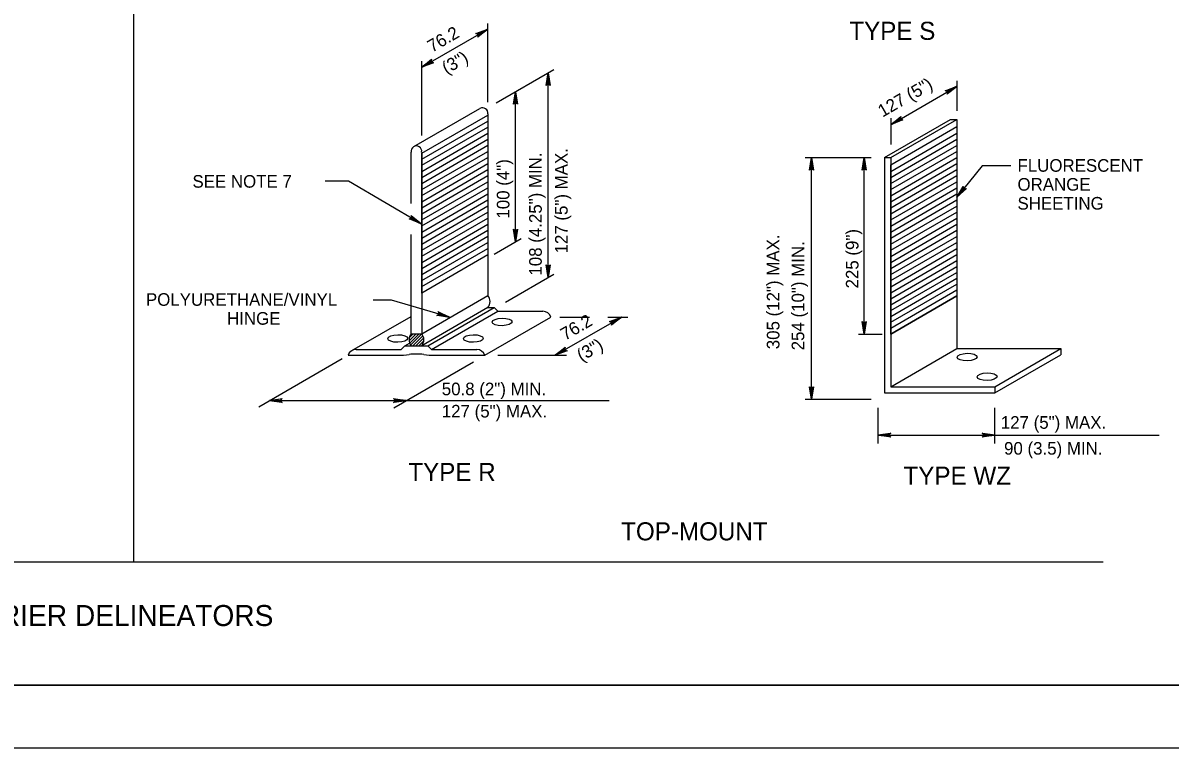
# Model space of a CAD drawing. Extents: x 640253 to 641999, y 298458 to 299646.
# Drawn here: x 640526.1 to 640798.8, y 298457.6 to 298630.1 of the extents above; entities that cross this region are included whole.
import ezdxf

# ---------------------------------------------------------------- set-up
doc = ezdxf.new("R2010")
doc.units = 0
for name, color, linetype in [('1', 7, 'Continuous'), ('2', 7, 'Continuous'), ('PLT-BNDY', 7, 'Continuous')]:
    doc.layers.add(name, color=color, linetype=linetype)

msp = doc.modelspace()

# ---------------------------------------------------------------- linework, layer by layer
at = {"layer": '1'}
for p, q in [((640552.4, 298501.97), (640552.4, 298787.67)), ((640318.26, 298501.97), (640782.88, 298501.97)), ((641079.31, 298472.63), (640293.31, 298472.63)), ((640293.31, 298472.63), (640879.31, 298472.63))]:
    msp.add_line(p, q, dxfattribs=at)
at = {"layer": '2'}
for p, q in [((640636.6, 298611.27), (640636.6, 298629.99)), ((640620.86, 298619.6), (640636.6, 298628.69)), ((640620.86, 298603.34), (640620.86, 298621.06)), ((640638.58, 298611.11), (640652.31, 298619.04)), ((640650.95, 298569.6), (640650.95, 298618.26)), ((640748.2, 298609.2), (640748.2, 298616.39)), ((640643.19, 298578.08), (640643.19, 298613.77)), ((640732.46, 298605.99), (640748.2, 298615.08)), ((640618.97, 298600.71), (640634.72, 298609.8)), ((640636.6, 298608.5), (640636.6, 298565.29)), ((640730.89, 298598.1), (640746.63, 298607.19)), ((640732.39, 298598.1), (640748.13, 298607.19)), ((640732.46, 298601.21), (640732.46, 298607.46)), ((640746.63, 298607.19), (640748.13, 298607.19)), ((640748.13, 298607.19), (640748.13, 298552.69)), ((640620.86, 298597.71), (640636.6, 298606.8)), ((640620.86, 298596.27), (640636.6, 298605.36)), ((640620.86, 298594.82), (640636.6, 298603.91)), ((640620.86, 298593.38), (640636.6, 298602.47)), ((640732.39, 298594.81), (640748.13, 298603.9)), ((640732.39, 298593.37), (640748.13, 298602.46)), ((640618.36, 298587.14), (640618.36, 298599.41)), ((640620.86, 298591.94), (640636.6, 298601.02)), ((640620.86, 298590.49), (640636.6, 298599.58)), ((640620.86, 298599.41), (640620.86, 298556.2)), ((640620.86, 298598.88), (640621.08, 298599.28)), ((640620.86, 298598.91), (640621.05, 298599.26)), ((640732.39, 298591.92), (640748.13, 298601.01)), ((640732.39, 298590.48), (640748.13, 298599.57)), ((640620.86, 298589.05), (640636.6, 298598.14)), ((640620.86, 298587.61), (640636.6, 298596.69)), ((640712.01, 298598.1), (640727.76, 298598.1)), ((640713.55, 298540.6), (640713.55, 298598.1)), ((640726.09, 298556.11), (640726.09, 298598.1)), ((640730.89, 298598.1), (640732.39, 298598.1)), ((640730.89, 298598.1), (640730.89, 298542.1)), ((640732.39, 298589.04), (640748.13, 298598.13)), ((640732.39, 298598.1), (640732.39, 298543.6)), ((640732.39, 298587.59), (640748.13, 298596.68)), ((640732.39, 298596.1), (640732.61, 298596.5)), ((640732.39, 298596.14), (640732.58, 298596.48)), ((640620.86, 298586.16), (640636.6, 298595.25)), ((640620.86, 298584.72), (640636.6, 298593.81)), ((640732.39, 298586.15), (640748.13, 298595.24)), ((640732.39, 298584.71), (640748.13, 298593.8)), ((640754.14, 298596.12), (640748.13, 298588.7)), ((640760.91, 298596.12), (640754.14, 298596.12)), ((640603.45, 298592.49), (640597.95, 298592.49)), ((640620.73, 298582.38), (640603.45, 298592.49)), ((640620.86, 298583.28), (640636.6, 298592.36)), ((640620.86, 298581.83), (640636.6, 298590.92)), ((640732.39, 298583.26), (640748.13, 298592.35)), ((640732.39, 298581.82), (640748.13, 298590.91)), ((640620.86, 298580.39), (640636.6, 298589.48)), ((640620.86, 298578.94), (640636.6, 298588.03)), ((640732.39, 298580.38), (640748.13, 298589.47)), ((640732.39, 298578.93), (640748.13, 298588.02)), ((640620.86, 298577.5), (640636.6, 298586.59)), ((640732.39, 298577.49), (640748.13, 298586.58)), ((640620.86, 298576.06), (640636.6, 298585.15)), ((640620.86, 298574.62), (640636.6, 298583.7)), ((640732.39, 298576.05), (640748.13, 298585.14)), ((640732.39, 298574.6), (640748.13, 298583.69)), ((640620.86, 298573.17), (640636.6, 298582.26)), ((640620.86, 298571.73), (640636.6, 298580.82)), ((640732.39, 298573.16), (640748.13, 298582.25)), ((640732.39, 298571.72), (640748.13, 298580.81)), ((640618.36, 298556.2), (640618.36, 298579.81)), ((640620.86, 298570.28), (640636.6, 298579.37)), ((640620.86, 298568.84), (640636.6, 298577.93)), ((640638.07, 298575.12), (640644.5, 298578.83)), ((640732.39, 298570.27), (640748.13, 298579.36)), ((640732.39, 298568.83), (640748.13, 298577.92)), ((640620.86, 298567.4), (640636.6, 298576.49)), ((640732.39, 298567.39), (640748.13, 298576.48)), ((640732.39, 298565.94), (640748.13, 298575.03)), ((640732.39, 298564.5), (640748.13, 298573.59)), ((640732.39, 298563.1), (640748.13, 298572.19)), ((640640.76, 298563.72), (640652.31, 298570.39)), ((640732.39, 298561.71), (640748.13, 298570.79)), ((640732.39, 298560.31), (640748.13, 298569.4)), ((640732.39, 298558.91), (640748.13, 298568)), ((640732.39, 298557.51), (640748.13, 298566.6)), ((640613.67, 298564.19), (640609.34, 298564.19)), ((640627.46, 298560.15), (640613.67, 298564.19)), ((640620.86, 298556.2), (640636.6, 298565.29)), ((640732.39, 298556.11), (640748.13, 298565.2)), ((640636.6, 298562.41), (640620.86, 298553.31)), ((640622.36, 298553.31), (640638.1, 298562.41)), ((640623.23, 298552.44), (640638.98, 298561.53)), ((640636.6, 298562.41), (640638.1, 298562.41)), ((640638.1, 298562.41), (640638.98, 298561.53)), ((640638.98, 298561.53), (640649.7, 298561.53)), ((640604.27, 298552.17), (640618.36, 298560.31)), ((640635.85, 298551.06), (640651.6, 298560.16)), ((640652.59, 298551.06), (640668.35, 298560.16)), ((640653.68, 298560.16), (640660.77, 298560.16)), ((640665.09, 298560.16), (640669.88, 298560.16)), ((640617.88, 298554.53), (640619.55, 298556.2)), ((640617.95, 298555.31), (640618.84, 298556.2)), ((640618.01, 298553.96), (640620.26, 298556.2)), ((640618.24, 298553.48), (640620.9, 298556.14)), ((640618.36, 298556.2), (640620.86, 298556.2)), ((640618.78, 298553.31), (640621.17, 298555.7)), ((640724.73, 298556.11), (640730.31, 298556.11)), ((640616.86, 298553.31), (640615.98, 298552.44)), ((640616.86, 298553.31), (640617.98, 298553.96)), ((640616.86, 298553.31), (640622.36, 298553.31)), ((640619.49, 298553.31), (640621.32, 298555.15)), ((640620.2, 298553.31), (640621.33, 298554.45)), ((640620.86, 298553.31), (640620.86, 298553.32)), ((640622.36, 298553.31), (640623.23, 298552.44)), ((640732.39, 298543.6), (640748.13, 298552.69)), ((640748.13, 298552.69), (640772.85, 298552.69)), ((640757.1, 298543.6), (640772.85, 298552.69)), ((640772.85, 298552.69), (640772.85, 298551.2)), ((640582.11, 298538.79), (640601.98, 298550.27)), ((640603.36, 298551.06), (640615.26, 298551.06)), ((640605.26, 298552.44), (640615.98, 298552.44)), ((640623.23, 298552.44), (640633.95, 298552.44)), ((640623.96, 298551.06), (640635.85, 298551.06)), ((640638.93, 298551.06), (640655.32, 298551.06)), ((640757.1, 298542.1), (640772.85, 298551.2)), ((640614.25, 298538.6), (640633.17, 298549.52)), ((640730.89, 298542.1), (640757.1, 298542.1)), ((640732.39, 298543.6), (640757.1, 298543.6)), ((640757.1, 298543.6), (640757.1, 298542.1)), ((640584.7, 298540.29), (640665.44, 298540.29)), ((640712.01, 298540.6), (640727.76, 298540.6)), ((640729.39, 298530.05), (640729.39, 298538.56)), ((640757.1, 298530.05), (640757.1, 298538.56)), ((640729.39, 298532.09), (640796.22, 298532.09))]:
    msp.add_line(p, q, dxfattribs=at)
for points in [[(640633.95, 298627.57), (640634.14, 298627.45), (640636.6, 298628.69), (640633.95, 298627.57), (640633.76, 298627.61), (640636.6, 298628.69), (640634.29, 298627.2), (640634.3, 298626.97), (640636.6, 298628.69), (640634.24, 298626.78), (640634.3, 298626.97)], [(640623.51, 298620.71), (640623.31, 298620.84), (640620.86, 298619.6), (640623.51, 298620.71), (640623.7, 298620.68), (640620.86, 298619.6), (640623.17, 298621.09), (640623.15, 298621.31), (640620.86, 298619.6), (640623.22, 298621.51), (640623.15, 298621.31)], [(640650.6, 298615.4), (640650.8, 298615.51), (640650.95, 298618.26), (640650.6, 298615.4), (640650.47, 298615.26), (640650.95, 298618.26), (640651.09, 298615.51), (640651.29, 298615.41), (640650.95, 298618.26), (640651.43, 298615.26), (640651.29, 298615.41)], [(640642.83, 298610.92), (640643.04, 298611.03), (640643.19, 298613.77), (640642.83, 298610.92), (640642.71, 298610.77), (640643.19, 298613.77), (640643.33, 298611.03), (640643.53, 298610.93), (640643.19, 298613.77), (640643.67, 298610.77), (640643.53, 298610.93)], [(640745.55, 298613.97), (640745.75, 298613.84), (640748.2, 298615.08), (640745.55, 298613.97), (640745.36, 298614), (640748.2, 298615.08), (640745.89, 298613.59), (640745.91, 298613.37), (640748.2, 298615.08), (640745.84, 298613.17), (640745.91, 298613.37)], [(640735.11, 298607.11), (640734.91, 298607.24), (640732.46, 298605.99), (640735.11, 298607.11), (640735.3, 298607.08), (640732.46, 298605.99), (640734.77, 298607.48), (640734.75, 298607.71), (640732.46, 298605.99), (640734.82, 298607.91), (640734.75, 298607.71)], [(640713.19, 298595.25), (640713.4, 298595.36), (640713.55, 298598.1), (640713.19, 298595.25), (640713.06, 298595.1), (640713.55, 298598.1), (640713.68, 298595.36), (640713.89, 298595.26), (640713.55, 298598.1), (640714.02, 298595.1), (640713.89, 298595.26)], [(640725.73, 298595.25), (640725.94, 298595.36), (640726.09, 298598.1), (640725.73, 298595.25), (640725.61, 298595.1), (640726.09, 298598.1), (640726.22, 298595.36), (640726.43, 298595.26), (640726.09, 298598.1), (640726.57, 298595.1), (640726.43, 298595.26)], [(640750.2, 298590.69), (640749.97, 298590.74), (640748.13, 298588.7), (640750.2, 298590.69), (640750.39, 298590.73), (640748.13, 298588.7), (640749.75, 298590.92), (640749.65, 298591.13), (640748.13, 298588.7), (640749.64, 298591.33), (640749.65, 298591.13)], [(640618.46, 298584.15), (640618.44, 298583.92), (640620.73, 298582.38), (640618.46, 298584.15), (640618.4, 298584.34), (640620.73, 298582.38), (640618.3, 298583.67), (640618.11, 298583.55), (640620.73, 298582.38), (640617.9, 298583.51), (640618.11, 298583.55)], [(640643.55, 298580.93), (640643.35, 298580.83), (640643.19, 298578.08), (640643.55, 298580.93), (640643.68, 298581.08), (640643.19, 298578.08), (640643.06, 298580.83), (640642.85, 298580.93), (640643.19, 298578.08), (640642.72, 298581.08), (640642.85, 298580.93)], [(640651.31, 298572.46), (640651.11, 298572.35), (640650.95, 298569.6), (640651.31, 298572.46), (640651.44, 298572.6), (640650.95, 298569.6), (640650.82, 298572.35), (640650.61, 298572.45), (640650.95, 298569.6), (640650.48, 298572.6), (640650.61, 298572.45)], [(640624.82, 298561.29), (640624.87, 298561.07), (640627.46, 298560.15), (640624.82, 298561.29), (640624.72, 298561.45), (640627.46, 298560.15), (640624.79, 298560.79), (640624.63, 298560.62), (640627.46, 298560.15), (640624.45, 298560.53), (640624.63, 298560.62)], [(640665.7, 298559.04), (640665.89, 298558.92), (640668.35, 298560.16), (640665.7, 298559.04), (640665.51, 298559.08), (640668.35, 298560.16), (640666.04, 298558.67), (640666.05, 298558.44), (640668.35, 298560.16), (640665.99, 298558.24), (640666.05, 298558.44)], [(640726.45, 298558.97), (640726.24, 298558.86), (640726.09, 298556.11), (640726.45, 298558.97), (640726.57, 298559.11), (640726.09, 298556.11), (640725.95, 298558.86), (640725.75, 298558.96), (640726.09, 298556.11), (640725.61, 298559.11), (640725.75, 298558.96)], [(640655.24, 298552.18), (640655.05, 298552.31), (640652.59, 298551.06), (640655.24, 298552.18), (640655.43, 298552.14), (640652.59, 298551.06), (640654.9, 298552.55), (640654.89, 298552.78), (640652.59, 298551.06), (640654.95, 298552.98), (640654.89, 298552.78)], [(640713.91, 298543.46), (640713.7, 298543.35), (640713.55, 298540.6), (640713.91, 298543.46), (640714.03, 298543.6), (640713.55, 298540.6), (640713.41, 298543.35), (640713.21, 298543.45), (640713.55, 298540.6), (640713.07, 298543.6), (640713.21, 298543.45)], [(640587.56, 298539.93), (640587.45, 298540.14), (640584.7, 298540.29), (640587.56, 298539.93), (640587.7, 298539.81), (640584.7, 298540.29), (640587.45, 298540.43), (640587.55, 298540.63), (640584.7, 298540.29), (640587.7, 298540.77), (640587.55, 298540.63)], [(640614.34, 298540.65), (640614.44, 298540.45), (640617.19, 298540.29), (640614.34, 298540.65), (640614.19, 298540.78), (640617.19, 298540.29), (640614.45, 298540.16), (640614.35, 298539.95), (640617.19, 298540.29), (640614.19, 298539.82), (640614.35, 298539.95)], [(640732.24, 298531.74), (640732.14, 298531.94), (640729.39, 298532.09), (640732.24, 298531.74), (640732.39, 298531.61), (640729.39, 298532.09), (640732.13, 298532.23), (640732.23, 298532.43), (640729.39, 298532.09), (640732.39, 298532.57), (640732.23, 298532.43)], [(640754.25, 298532.45), (640754.36, 298532.25), (640757.1, 298532.09), (640754.25, 298532.45), (640754.1, 298532.58), (640757.1, 298532.09), (640754.36, 298531.96), (640754.26, 298531.76), (640757.1, 298532.09), (640754.1, 298531.62), (640754.26, 298531.76)]]:
    msp.add_lwpolyline(points, dxfattribs=at)
for points in [[(640620.86, 298565.88), (640620.86, 298599.14), (640636.6, 298608.23), (640636.6, 298574.97)], [(640732.39, 298556.11), (640732.39, 298596.37), (640748.13, 298605.46), (640748.13, 298565.2)]]:
    msp.add_lwpolyline(points, close=True, dxfattribs=at)
for centre, radius, start, end in [((640635.35, 298608.7), 1.26, 350.9133, 119.9792), ((640619.61, 298599.61), 1.26, 350.9133, 189.0867), ((640634.82, 298563.85), 2.29, 320.9923, 39.0623), ((640649.7, 298559.53), 2, 18.187, 90), ((640620.14, 298554.76), 2.29, 140.9377, 219.0623), ((640619.08, 298554.76), 2.29, 320.9923, 39.0623), ((640605.26, 298550.44), 2, 90, 161.79), ((640615.26, 298569.81), 18.75, 270, 278.0038), ((640619.61, 298538.87), 12.5, 81.9962, 98.0038), ((640623.96, 298569.81), 18.75, 261.9962, 270), ((640633.95, 298550.44), 2, 18.21, 90)]:
    msp.add_arc(centre, radius, start, end, dxfattribs=at)
for centre in [(640639.98, 298559.01), (640615.17, 298555.06), (640633.14, 298555.06), (640750.54, 298550.64), (640755.3, 298545.98)]:
    msp.add_ellipse(centre, major_axis=(2.36, 0.05), ratio=0.379302, dxfattribs=at)
at = {"layer": 'PLT-BNDY'}
msp.add_lwpolyline([(640253.31, 299051.63), (641094.31, 299051.63), (641094.31, 298457.63), (640253.31, 298457.63)], close=True, dxfattribs=at)

# ---------------------------------------------------------------- texts
at = {"layer": '2'}
for s, rotation, p in [('76.2', 30, (640623.33, 298623.01)), ('(3")', 30, (640626.77, 298617.86)), ('127 (5")', 30, (640730.43, 298607.6)), ('108 (4.25") MIN.', 90, (640649.41, 298570.03)), ('127 (5") MAX.', 90, (640655.57, 298575.3)), ('100 (4")', 90, (640641.72, 298583.59)), ('225 (9")', 90, (640724.72, 298566.97)), ('305 (12") MAX.', 90, (640705.92, 298552.51)), ('254 (10") MIN.', 90, (640711.82, 298552.25)), ('76.2', 30, (640654.97, 298554.49)), ('(3")', 30, (640658.85, 298549.49))]:
    msp.add_text(s, height=3, rotation=rotation, dxfattribs=at).set_placement(p)
for s, height, p in [('TYPE S', 4.3, (640722.54, 298626.11)), ('FLUORESCENT', 3, (640762.52, 298594.73)), ('SEE NOTE 7', 3, (640566.35, 298590.94)), ('ORANGE', 3, (640762.52, 298590.23)), ('SHEETING', 3, (640762.52, 298585.73)), ('POLYURETHANE/VINYL', 3, (640555.3, 298562.84)), ('HINGE', 3, (640574.58, 298558.34)), ('50.8 (2") MIN.', 3, (640625.64, 298541.56)), ('127 (5") MAX.', 3, (640625.64, 298536.27)), ('127 (5") MAX.', 3, (640758.56, 298533.59)), ('90 (3.5) MIN.', 3, (640759.33, 298527.43)), ('TYPE R', 4.3, (640617.68, 298521.17)), ('TYPE WZ', 4.3, (640735.42, 298520.28)), ('TOP-MOUNT', 4.3, (640668.29, 298507.04)), ('BARRIER DELINEATORS', 5, (640506.83, 298486.66))]:
    msp.add_text(s, height=height, dxfattribs=at).set_placement(p)

doc.saveas('drawing.dxf')
